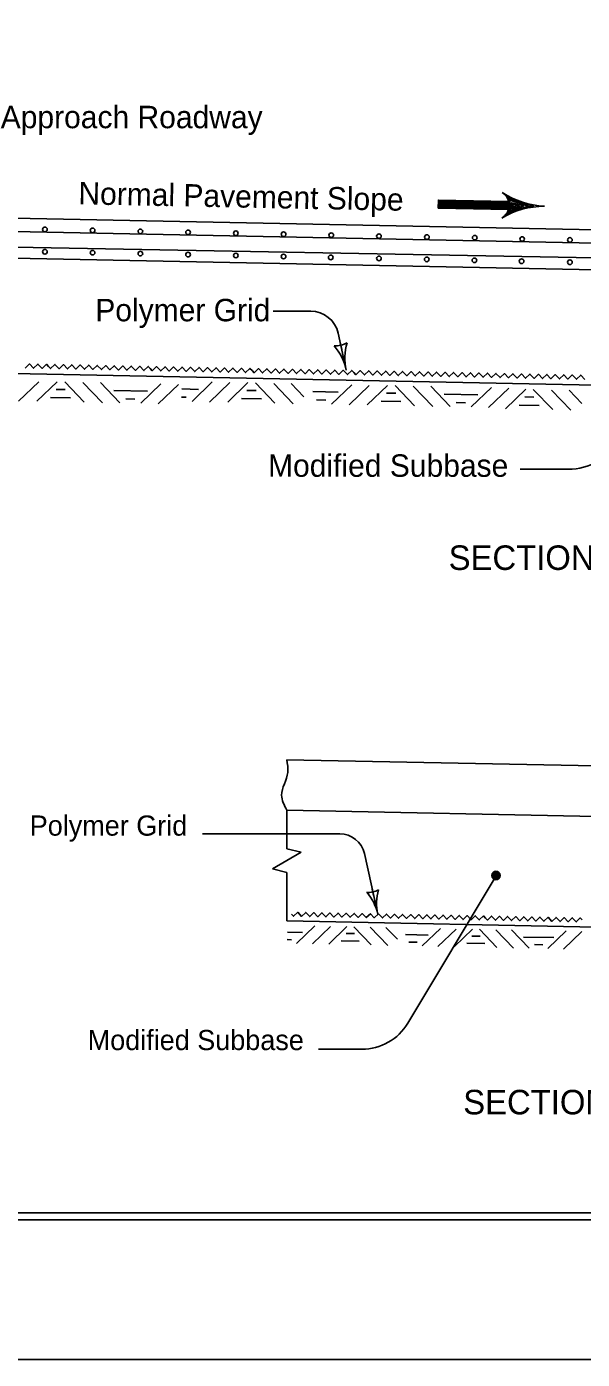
# Model space of a CAD drawing. Extents: x 10028 to 81668, y 6395 to 11634.
# Drawn here: x 14208 to 14605, y 7825 to 8776 of the extents above; entities that cross this region are included whole.
import ezdxf

# ---------------------------------------------------------------- set-up
doc = ezdxf.new("R2010")
doc.units = 0
for name, color, linetype in [('Default', 7, 'Continuous'), ('dsnCellElements', 7, 'Continuous'), ('dsnstdblockInterim', 7, 'Continuous'), ('dsnStdDimension', 7, 'Continuous'), ('ShtPlotIdentification', 7, 'Continuous')]:
    doc.layers.add(name, color=color, linetype=linetype)

msp = doc.modelspace()

# ---------------------------------------------------------------- linework, layer by layer
at = {"layer": 'Default'}
msp.add_lwpolyline([(13732.53, 9944.02), (16867.53, 9944.02), (16867.53, 7924.02), (13732.53, 7924.02)], close=True, dxfattribs=at)
at = {"layer": 'dsnCellElements'}
msp.add_line((14901.95, 8605.39), (14170.4, 8618.94), dxfattribs=at)
at = {"layer": 'dsnstdblockInterim'}
msp.add_lwpolyline([(13732.53, 9939.02), (16867.53, 9939.02), (16867.53, 7929.02), (13732.53, 7929.02)], close=True, dxfattribs=at)
at = {"layer": 'dsnStdDimension'}
msp.add_lwpolyline([(13628.03, 7824.52), (16972.03, 7824.52), (16972.03, 10408.52), (13628.03, 10408.52)], close=True, dxfattribs=at)
at = {"layer": 'ShtPlotIdentification'}
for p, q in [((14552.11, 8648.07), (14501.98, 8649.08)), ((14552.03, 8651.1), (14552.03, 8651.1)), ((14880.69, 8625.23), (14170.44, 8639.49)), ((14170.44, 8639.49), (14880.69, 8625.23)), ((14551.96, 8645.24), (14551.96, 8645.24)), ((14170.4, 8630), (14902.07, 8615.32)), ((14169.87, 8611.13), (14918.97, 8596.1)), ((14171.01, 8611.11), (14918.97, 8596.1)), ((14384.16, 8572.6), (14410.97, 8572.6)), ((14430.5, 8556.9), (14436.31, 8530.53)), ((14431.92, 8550.45), (14433.05, 8545.34)), ((14170.44, 8528.7), (14987.03, 8512.31)), ((14217.1, 8522.28), (14202.68, 8508.42)), ((14230.11, 8522.24), (14215.69, 8508.39)), ((14235.52, 8522.14), (14249.38, 8507.71)), ((14248.52, 8521.65), (14262.38, 8507.23)), ((14260.97, 8521.62), (14274.83, 8507.2)), ((14304.19, 8520.76), (14289.77, 8506.9)), ((14316.63, 8520.28), (14302.21, 8506.43)), ((14340.73, 8522.12), (14326.3, 8508.26)), ((14353.17, 8521.64), (14338.75, 8507.78)), ((14366.18, 8521.6), (14351.76, 8507.75)), ((14371.59, 8521.5), (14385.45, 8507.07)), ((14384.59, 8521.01), (14398.45, 8506.59)), ((14397.04, 8520.99), (14406.14, 8511.51)), ((14440.26, 8520.12), (14425.84, 8506.26)), ((14452.7, 8519.64), (14438.28, 8505.79)), ((14465.71, 8519.61), (14451.29, 8505.75)), ((14471.12, 8519.5), (14484.98, 8505.08)), ((14484.12, 8519.01), (14497.98, 8504.59)), ((14496.58, 8518.99), (14510.43, 8504.56)), ((14539.79, 8518.12), (14525.37, 8504.26)), ((14552.23, 8517.64), (14537.81, 8503.79)), ((14564.28, 8516.89), (14549.86, 8503.03)), ((14569.69, 8516.78), (14583.55, 8502.36)), ((14582.69, 8516.29), (14596.55, 8501.87)), ((14595.15, 8516.27), (14604.25, 8506.8)), ((14560.3, 8459.77), (14594.58, 8459.77)), ((14729.51, 8245.72), (14393.87, 8252.46)), ((14393.87, 8252.46), (14804.18, 8244.22)), ((14393.87, 8216.45), (14729.51, 8209.71)), ((14393.87, 8216.45), (14876.36, 8206.77)), ((14393.87, 8216.22), (14393.87, 8188.98)), ((14333.74, 8199.59), (14431.66, 8199.59)), ((14393.87, 8180.48), (14383.66, 8174.52)), ((14393.87, 8188.98), (14404.08, 8186.43)), ((14404.08, 8186.43), (14393.87, 8180.48)), ((14449.23, 8185.47), (14458.78, 8142.15)), ((14383.66, 8174.52), (14393.87, 8171.96)), ((14393.87, 8171.96), (14393.87, 8137.48)), ((14480.25, 8064.47), (14543.08, 8169.56)), ((14454.83, 8160.08), (14455.84, 8155.48)), ((14393.87, 8137.48), (14962.76, 8126.06)), ((14413.91, 8133.87), (14400.93, 8121.4)), ((14425.11, 8133.44), (14412.13, 8120.97)), ((14436.82, 8133.41), (14423.84, 8120.94)), ((14441.69, 8133.31), (14454.16, 8120.33)), ((14453.39, 8132.87), (14465.86, 8119.89)), ((14464.6, 8132.85), (14472.79, 8124.32)), ((14503.49, 8132.07), (14490.51, 8119.6)), ((14514.69, 8131.64), (14501.71, 8119.17)), ((14526.4, 8131.61), (14513.42, 8119.14)), ((14531.27, 8131.51), (14543.74, 8118.53)), ((14542.97, 8131.07), (14555.44, 8118.09)), ((14554.18, 8131.05), (14566.65, 8118.07)), ((14593.07, 8130.27), (14580.09, 8117.8)), ((14604.27, 8129.84), (14591.29, 8117.37)), ((14416.54, 8045.83), (14447.39, 8045.83))]:
    msp.add_line(p, q, dxfattribs=at)
for points in [[(14552.08, 8650.91), (14502.04, 8651.92), (14501.92, 8646.25), (14551.96, 8645.24), (14551.9, 8650.1), (14502.67, 8651.28), (14502.7, 8646.76), (14550.87, 8645.98), (14551.07, 8649.36), (14503.34, 8650.51), (14503.41, 8647.5), (14550.26, 8646.56), (14550.43, 8648.69), (14503.9, 8649.87), (14503.92, 8648.18), (14549.65, 8647.33)], [(14550.8, 8654.63), (14552.86, 8651.21), (14553.01, 8646.25), (14551.11, 8641.97), (14558.56, 8644.89), (14567.26, 8647.22), (14569.71, 8647.74), (14563.47, 8649.11), (14554.45, 8652.43), (14551.79, 8653.92), (14552.58, 8643.38), (14566.01, 8647.62), (14553.06, 8651.83), (14553.41, 8644.55), (14562.62, 8647.75), (14554.28, 8649.99), (14553.82, 8645.8), (14559.68, 8647.56), (14555.26, 8648.9), (14554.97, 8646.9), (14557.11, 8647.49)], [(14207.27, 8531.97), (14210.36, 8534.93), (14213.32, 8531.85), (14216.4, 8534.81), (14219.36, 8531.73), (14222.45, 8534.7), (14223.94, 8533.15)], [(14223.94, 8533.15), (14225.42, 8531.61), (14228.5, 8534.57), (14231.47, 8531.49), (14234.55, 8534.45), (14237.51, 8531.36), (14240.6, 8534.33), (14243.56, 8531.24), (14246.64, 8534.21), (14249.61, 8531.13), (14252.69, 8534.09), (14255.66, 8531), (14258.74, 8533.96), (14261.71, 8530.88), (14264.79, 8533.84), (14267.76, 8530.76), (14270.84, 8533.73), (14273.8, 8530.64), (14276.89, 8533.6), (14279.85, 8530.52), (14282.94, 8533.48), (14285.91, 8530.39), (14288.99, 8533.36), (14291.95, 8530.27), (14295.04, 8533.24), (14296.52, 8531.69)], [(14296.52, 8531.69), (14298, 8530.15), (14301.08, 8533.12), (14304.05, 8530.03), (14307.13, 8532.99), (14310.1, 8529.91), (14313.19, 8532.87), (14316.15, 8529.79), (14319.23, 8532.75), (14322.19, 8529.67), (14325.28, 8532.63), (14328.24, 8529.55), (14331.33, 8532.51), (14334.3, 8529.42), (14337.38, 8532.39), (14340.34, 8529.3), (14343.43, 8532.27), (14346.39, 8529.18), (14349.47, 8532.14), (14352.44, 8529.06), (14355.52, 8532.02), (14358.49, 8528.94), (14361.57, 8531.9), (14364.54, 8528.82), (14367.62, 8531.78), (14369.1, 8530.24)], [(14369.1, 8530.24), (14370.58, 8528.7), (14373.67, 8531.66), (14376.63, 8528.57), (14379.72, 8531.54), (14382.68, 8528.45), (14385.77, 8531.42), (14388.73, 8528.33), (14391.82, 8531.3), (14394.78, 8528.21), (14397.86, 8531.17), (14400.83, 8528.09), (14403.91, 8531.05), (14406.88, 8527.97), (14409.96, 8530.93), (14412.93, 8527.85), (14416.01, 8530.81), (14418.97, 8527.73), (14422.06, 8530.69), (14425.02, 8527.6), (14428.11, 8530.57), (14431.07, 8527.48), (14434.16, 8530.45), (14437.12, 8527.36), (14440.21, 8530.33), (14441.69, 8528.78)], [(14441.69, 8528.78), (14443.17, 8527.24), (14446.25, 8530.2), (14449.22, 8527.12), (14452.3, 8530.08), (14455.27, 8526.99), (14458.35, 8529.96), (14461.32, 8526.87), (14464.4, 8529.84), (14467.36, 8526.76), (14470.45, 8529.72), (14473.41, 8526.63), (14476.5, 8529.59), (14479.46, 8526.51), (14482.55, 8529.47), (14485.51, 8526.39), (14488.6, 8529.35), (14491.56, 8526.27), (14494.65, 8529.23), (14497.61, 8526.15), (14500.69, 8529.11), (14503.66, 8526.02), (14506.74, 8528.99), (14509.71, 8525.9), (14512.79, 8528.87), (14514.27, 8527.32)], [(14514.27, 8527.32), (14515.76, 8525.78), (14518.84, 8528.75), (14521.8, 8525.66), (14524.89, 8528.62), (14527.85, 8525.54), (14530.94, 8528.5), (14533.9, 8525.42), (14536.99, 8528.38), (14539.95, 8525.3), (14543.04, 8528.26), (14546, 8525.18), (14549.08, 8528.14), (14552.05, 8525.05), (14555.13, 8528.02), (14558.1, 8524.93), (14561.18, 8527.9), (14564.15, 8524.81), (14567.23, 8527.78), (14570.19, 8524.69), (14573.28, 8527.65), (14576.24, 8524.57), (14579.33, 8527.53), (14582.29, 8524.45), (14585.38, 8527.41), (14586.86, 8525.87)], [(14586.86, 8525.87), (14588.34, 8524.33), (14591.42, 8527.29), (14594.39, 8524.2), (14597.47, 8527.17), (14600.44, 8524.08), (14603.52, 8527.05), (14606.49, 8523.96)], [(14229.44, 8516.76), (14235.97, 8516.63)], [(14270.44, 8515.96), (14294.5, 8515.48)], [(14319.01, 8517.08), (14331.04, 8516.83)], [(14365.51, 8516.12), (14372.04, 8515.99)], [(14412.51, 8515.2), (14430.57, 8514.84)], [(14465.04, 8514.12), (14471.57, 8513.99)], [(14506.05, 8513.32), (14530.1, 8512.84)], [(14225.49, 8510.98), (14239.68, 8510.7)], [(14279.09, 8509.98), (14285.62, 8509.85)], [(14318.89, 8511.28), (14322.16, 8511.21)], [(14361.56, 8510.34), (14375.75, 8510.06)], [(14415.16, 8509.34), (14421.69, 8509.21)], [(14461.09, 8508.34), (14475.28, 8508.06)], [(14514.69, 8507.35), (14521.22, 8507.22)], [(14559.66, 8505.62), (14573.85, 8505.34)], [(14563.61, 8511.4), (14570.14, 8511.27)], [(14542.83, 8167.12), (14543.84, 8167.57), (14545.4, 8168.06), (14545.7, 8169.64), (14545.49, 8171.03), (14544.49, 8172.32), (14543, 8172.19), (14541.43, 8171.97), (14540.68, 8170.72), (14540.54, 8169.4), (14541.47, 8167.68), (14542.61, 8167.54), (14544.18, 8167.93), (14545.46, 8168.93), (14545.42, 8170.42), (14544.42, 8171.62), (14543.01, 8171.75), (14541.45, 8171.44), (14541.21, 8170.56), (14540.89, 8169.5), (14541.63, 8168.21), (14542.77, 8168.24), (14544.07, 8168.45), (14545.02, 8169.18), (14544.54, 8170.48), (14543.55, 8171.24), (14542.24, 8171.29), (14541.91, 8170.58), (14541.49, 8169.78), (14542.14, 8168.75), (14543.11, 8168.51), (14543.97, 8168.98), (14544.03, 8169.94), (14543.57, 8170.63), (14542.69, 8170.86), (14542.26, 8170.5), (14542.01, 8169.97), (14542.47, 8169.2), (14543.09, 8169.04), (14543.69, 8169.41), (14543.6, 8169.93), (14543.15, 8170.27), (14542.54, 8170.25), (14542.55, 8169.81), (14543.08, 8169.56)], [(14397.3, 8142.28), (14398.71, 8140.81), (14401.65, 8143.63), (14404.47, 8140.69), (14407.41, 8143.52), (14410.23, 8140.58), (14413.17, 8143.4), (14415.99, 8140.46), (14418.93, 8143.28), (14421.75, 8140.35), (14424.68, 8143.17), (14427.51, 8140.23), (14430.44, 8143.05), (14433.26, 8140.12), (14436.2, 8142.94), (14439.02, 8140), (14441.96, 8142.82), (14444.78, 8139.89), (14447.72, 8142.71), (14450.54, 8139.77), (14453.48, 8142.59), (14456.3, 8139.65), (14459.24, 8142.48), (14462.06, 8139.54), (14465, 8142.36), (14466.41, 8140.89)], [(14466.41, 8140.89), (14467.82, 8139.42), (14470.76, 8142.24), (14473.58, 8139.31), (14476.51, 8142.13), (14479.34, 8139.19), (14482.27, 8142.01), (14485.09, 8139.08), (14488.03, 8141.9), (14490.85, 8138.96), (14493.79, 8141.78), (14496.61, 8138.84), (14499.55, 8141.67), (14502.37, 8138.73), (14505.31, 8141.55), (14508.13, 8138.61), (14511.07, 8141.43), (14513.89, 8138.5), (14516.83, 8141.32), (14519.65, 8138.38), (14522.58, 8141.2), (14525.41, 8138.27), (14528.34, 8141.09), (14531.17, 8138.15), (14534.1, 8140.97), (14535.51, 8139.5)], [(14535.51, 8139.5), (14536.92, 8138.04), (14539.86, 8140.86), (14542.68, 8137.92), (14545.62, 8140.74), (14548.44, 8137.8), (14551.38, 8140.63), (14554.2, 8137.69), (14557.14, 8140.51), (14559.96, 8137.57), (14562.9, 8140.39), (14565.72, 8137.46), (14568.66, 8140.28), (14571.48, 8137.34), (14574.41, 8140.16), (14577.24, 8137.23), (14580.17, 8140.05), (14582.99, 8137.11), (14585.93, 8139.93), (14588.75, 8137), (14591.69, 8139.82), (14594.51, 8136.88), (14597.45, 8139.7), (14600.27, 8136.76), (14603.21, 8139.59), (14604.62, 8138.12)], [(14394.26, 8124.11), (14397.2, 8124.05)], [(14394.37, 8129.33), (14405.19, 8129.11)], [(14432.67, 8123.27), (14445.44, 8123.01)], [(14436.22, 8128.47), (14442.1, 8128.35)], [(14478.52, 8127.64), (14494.77, 8127.32)], [(14525.8, 8126.67), (14531.68, 8126.55)], [(14562.7, 8125.95), (14584.35, 8125.52)], [(14480.9, 8122.37), (14486.78, 8122.26)], [(14522.24, 8121.47), (14535.02, 8121.22)], [(14570.48, 8120.58), (14576.36, 8120.46)]]:
    msp.add_lwpolyline(points, dxfattribs=at)
for centre, radius in [((14221.4, 8630.96), 1.65), ((14255.43, 8630.27), 1.65), ((14289.47, 8629.59), 1.65), ((14323.5, 8628.91), 1.65), ((14357.54, 8628.23), 1.65), ((14391.57, 8627.54), 1.65), ((14425.6, 8626.86), 1.65), ((14459.63, 8626.18), 1.65), ((14493.83, 8625.48), 1.65), ((14527.91, 8625.09), 1.65), ((14561.73, 8624.13), 1.65), ((14595.76, 8623.44), 1.65), ((14221.4, 8615.07), 1.65), ((14255.44, 8614.39), 1.65), ((14289.47, 8613.71), 1.65), ((14323.5, 8613.02), 1.65), ((14357.53, 8612.34), 1.65), ((14391.57, 8611.66), 1.65), ((14425.21, 8611.02), 1.65), ((14459.63, 8610.29), 1.65), ((14493.66, 8609.61), 1.65), ((14527.7, 8608.92), 1.65), ((14561.34, 8608.28), 1.65), ((14595.76, 8607.56), 1.65), ((14543.07, 8169.85), 2.98)]:
    msp.add_circle(centre, radius, dxfattribs=at)
for centre, radius, start, end in [((14541.74, 8648.28), 10.67, 300.56474, 57.13538), ((14580.6, 8708.44), 60.95, 237.1358, 267.16583), ((14578.16, 8586.61), 60.95, 90.53429, 120.56432), ((14410.97, 8552.6), 20, 12.43142, 90), ((14429.07, 8563.43), 15.52, 264.68499, 300.15169), ((14397.08, 8521.89), 40.18, 12.41834, 40.49083), ((14475.55, 8539.17), 40.18, 164.34585, 192.41834), ((14594.58, 8502.31), 42.54, 270, 329.12488), ((14431.66, 8181.59), 18, 12.43134, 90), ((14452.26, 8171.76), 13.97, 264.68499, 300.15169), ((14423.47, 8134.38), 36.16, 12.41834, 40.49083), ((14494.09, 8149.93), 36.16, 164.34585, 192.41834), ((14447.39, 8084.11), 38.28, 270, 329.12488)]:
    msp.add_arc(centre, radius, start, end, dxfattribs=at)
msp.add_spline([(14393.87, 8252.46), (14394.61, 8243.44), (14390.22, 8227.2), (14393.87, 8216.45)], degree=3, dxfattribs=at)
msp.add_spline([(14393.87, 8252.46), (14394.61, 8243.44), (14390.22, 8227.2), (14393.87, 8216.45)], degree=3, dxfattribs=at)

# ---------------------------------------------------------------- texts
at = {"layer": 'dsnCellElements'}
for s, height, p in [('Approach Roadway', 16, (14189.9, 8703.2)), ('Polymer Grid', 16, (14257.34, 8565.4)), ('Modified Subbase', 16, (14380.55, 8454.42)), ('Polymer Grid', 14.4, (14210.57, 8198.29)), ('Modified Subbase', 14.4, (14251.9, 8045.22))]:
    msp.add_text(s, height=height, dxfattribs=at).set_placement(p)
msp.add_text('Normal Pavement Slope', height=16, rotation=358.85018, dxfattribs=at).set_placement((14245.18, 8648.91))
at = {"layer": 'ShtPlotIdentification'}
for s, p in [('SECTION A-A', (14509.31, 8387.94)), ('SECTION B-B', (14519.72, 7999.36))]:
    msp.add_text(s, height=17.5, dxfattribs=at).set_placement(p)

doc.saveas('drawing.dxf')
